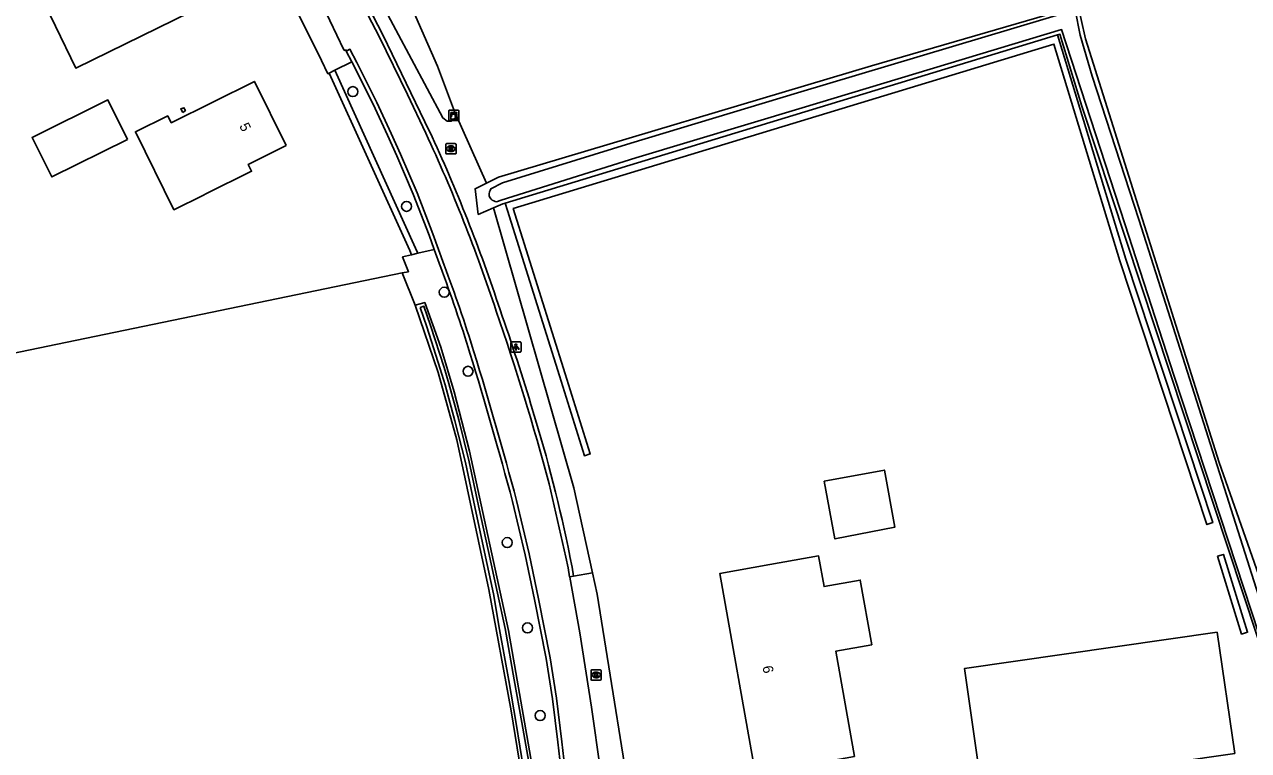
# Model space of a CAD drawing. Extents: x 162515 to 163909, y 388494 to 389773.
# Drawn here: x 163081.8 to 163201.7, y 389600.1 to 389671.2 of the extents above; entities that cross this region are included whole.
import ezdxf

# ---------------------------------------------------------------- set-up
doc = ezdxf.new("R2010")
doc.units = 0
for name, color, linetype in [('IMGEO_Boom', 7, 'Continuous'), ('IMGEO_Erf', 7, 'Continuous'), ('IMGEO_Grasland_agrarisch', 7, 'Continuous'), ('IMGEO_Grasland_overig', 7, 'Continuous'), ('IMGEO_Haag', 7, 'Continuous'), ('IMGEO_Kast', 7, 'Continuous'), ('IMGEO_Kolk', 7, 'Continuous'), ('IMGEO_Lichtpunt', 7, 'Continuous'), ('IMGEO_Pand', 7, 'Continuous'), ('IMGEO_Pand_nummerreeks', 7, 'Continuous'), ('IMGEO_Rijbaan_lokaal_gesloten', 7, 'Continuous'), ('IMGEO_Rijbaan_lokaal_halfverhard', 7, 'Continuous'), ('IMGEO_Rijbaan_lokaal_open', 7, 'Continuous'), ('IMGEO_Rioolput', 7, 'Continuous'), ('IMGEO_Sloot', 7, 'Continuous'), ('IMGEO_Waterloop', 7, 'Continuous')]:
    doc.layers.add(name, color=color, linetype=linetype)

msp = doc.modelspace()

# ---------------------------------------------------------------- linework, layer by layer
at = {"layer": 'IMGEO_Boom'}
for centre in [(163113.98, 389664.61), (163119.24, 389653.38), (163122.93, 389644.98), (163125.26, 389637.24), (163129.1, 389620.48), (163131.08, 389612.13), (163132.32, 389603.55)]:
    msp.add_circle(centre, 0.489, dxfattribs=at)
at = {"layer": 'IMGEO_Erf'}
for points in [[(163182.98, 389670.17), (163183.2, 389670.23), (163185.36, 389663.19), (163202.54, 389611.21), (163206.56, 389587.55), (163208.34, 389574.96), (163210.99, 389575.22)], [(163127.75, 389653.25), (163128.66, 389653.64), (163128.88, 389653.71)]]:
    msp.add_lwpolyline(points, dxfattribs=at)
at = {"layer": 'IMGEO_Grasland_agrarisch'}
for points in [[(163118.81, 389646.87), (163066.29, 389636.03), (163063.36, 389648.6), (163049.05, 389695.77), (163050.19, 389696.14), (163051.31, 389696.5), (163053.35, 389697.16), (163060.78, 389699.57), (163079.14, 389705.13), (163083.99, 389706.6)], [(163127.06, 389655.65), (163128.25, 389656.23), (163164.76, 389667.14), (163184.98, 389673), (163185.27, 389671.67)], [(163204.95, 389610.01), (163204.59, 389611.79), (163198.78, 389628.32), (163185.7, 389669.77), (163185.27, 389671.67)], [(163130.74, 389593.91), (163130.82, 389595.75), (163129.49, 389604.01), (163127.31, 389615.89), (163124.17, 389630.54), (163122.35, 389637.11), (163120.08, 389643.72)]]:
    msp.add_lwpolyline(points, dxfattribs=at)
at = {"layer": 'IMGEO_Grasland_overig'}
for points in [[(163127.06, 389655.65), (163123.95, 389662.66)], [(163127.75, 389653.25), (163126.26, 389652.6), (163125.95, 389655.11), (163127.06, 389655.65)], [(163137.44, 389617.53), (163135.63, 389625.83), (163127.75, 389653.25)], [(163120.34, 389648.79), (163121.96, 389649.17)], [(163119.74, 389648.65), (163118.86, 389648.44), (163119.43, 389646.99), (163118.81, 389646.87)], [(163120.08, 389643.72), (163118.81, 389646.87)], [(163120.08, 389643.72), (163120.56, 389643.84), (163121.03, 389643.96), (163122.6, 389639.6), (163123.9, 389635.22), (163125.4, 389629.44), (163129.21, 389611.86), (163131.99, 389595.99), (163132.04, 389595.09), (163132.1, 389594.03)]]:
    msp.add_lwpolyline(points, dxfattribs=at)
at = {"layer": 'IMGEO_Haag'}
for points in [[(163128.88, 389653.71), (163129.11, 389652.98), (163134.21, 389636.8), (163136.65, 389628.98), (163137.23, 389629.16), (163134.78, 389636.98), (163129.68, 389653.16), (163182.62, 389669.26), (163189.08, 389648.04), (163197.59, 389622.24), (163198.16, 389622.43), (163189.65, 389648.22), (163182.98, 389670.17)], [(163182.98, 389670.17), (163128.88, 389653.71)], [(163111.68, 389666.43), (163119.56, 389649.05), (163119.74, 389648.65)], [(163112.22, 389666.7), (163120.11, 389649.3), (163120.34, 389648.79)], [(163119.74, 389648.65), (163120.34, 389648.79)], [(163198.64, 389619.15), (163200.99, 389611.52), (163201.57, 389611.7), (163199.21, 389619.32), (163198.64, 389619.15)]]:
    msp.add_lwpolyline(points, dxfattribs=at)
at = {"layer": 'IMGEO_Kast'}
for p, q in [((163123.37, 389661.86), (163123.37, 389662.71)), ((163123.37, 389662.71), (163123.37, 389661.86)), ((163123.44, 389662.79), (163124.28, 389662.79)), ((163124.28, 389662.79), (163123.44, 389662.79)), ((163124.37, 389662.72), (163124.37, 389661.87)), ((163124.37, 389661.87), (163124.37, 389662.72)), ((163124.29, 389661.79), (163123.45, 389661.79)), ((163123.45, 389661.79), (163124.29, 389661.79))]:
    msp.add_line(p, q, dxfattribs=at)
for points in [[(163123.56, 389662.58), (163124.16, 389662.58), (163124.16, 389662.49), (163123.56, 389662.49), (163123.56, 389662.58)], [(163123.56, 389662.41), (163124.16, 389662.41), (163124.16, 389661.92), (163123.56, 389661.92), (163123.56, 389662.41)]]:
    msp.add_lwpolyline(points, dxfattribs=at)
msp.add_circle((163123.65, 389662.25), 0.0377, dxfattribs=at)
for centre, start, end in [((163123.45, 389662.71), 92.4484, 184.2845), ((163123.45, 389662.71), 92.4484, 184.2845), ((163124.29, 389662.71), 2.4484, 94.2845), ((163124.29, 389662.71), 2.4484, 94.2845), ((163123.45, 389661.87), 182.4484, 274.2845), ((163123.45, 389661.87), 182.4484, 274.2845), ((163124.29, 389661.87), 272.4484, 4.2845), ((163124.29, 389661.87), 272.4484, 4.2845)]:
    msp.add_arc(centre, 0.0779, start, end, dxfattribs=at)
at = {"layer": 'IMGEO_Kolk'}
for p, q in [((163137.37, 389608.03), (163138.22, 389608.03)), ((163137.3, 389607.1), (163137.3, 389607.96)), ((163138.22, 389607.03), (163137.37, 389607.03)), ((163137.78, 389607.81), (163137.81, 389607.81)), ((163137.81, 389607.25), (163137.78, 389607.25)), ((163138.3, 389607.96), (163138.3, 389607.1))]:
    msp.add_line(p, q, dxfattribs=at)
for points in [[(163137.37, 389608.03), (163138.22, 389608.03)], [(163137.3, 389607.1), (163137.3, 389607.96)], [(163138.22, 389607.03), (163137.37, 389607.03)], [(163137.62, 389607.73), (163137.74, 389607.73), (163137.74, 389607.58), (163137.87, 389607.73), (163138.03, 389607.73), (163137.89, 389607.58), (163138.04, 389607.33), (163137.89, 389607.33), (163137.8, 389607.49), (163137.74, 389607.43), (163137.74, 389607.33), (163137.62, 389607.33), (163137.62, 389607.73)], [(163138.3, 389607.96), (163138.3, 389607.1)]]:
    msp.add_lwpolyline(points, dxfattribs=at)
for centre, start, end in [((163137.37, 389607.95), 91.552, 178.448), ((163137.37, 389607.95), 91.552, 178.448), ((163138.22, 389607.95), 1.552, 88.448), ((163138.22, 389607.95), 1.552, 88.448), ((163137.37, 389607.1), 181.552, 268.448), ((163137.37, 389607.1), 181.552, 268.448), ((163138.22, 389607.1), 271.552, 358.448), ((163138.22, 389607.1), 271.552, 358.448)]:
    msp.add_arc(centre, 0.0765, start, end, dxfattribs=at)
for centre, major_axis, ratio, start_param, end_param in [((163137.78, 389607.53), (-0.387, 0.002), 0.722429, 4.712389, 7.853982), ((163137.81, 389607.53), (-0.39, 0.002), 0.717154, 1.570796, 4.712389)]:
    msp.add_ellipse(centre, major_axis=major_axis, ratio=ratio, start_param=start_param, end_param=end_param, dxfattribs=at)
at = {"layer": 'IMGEO_Lichtpunt'}
for p, q in [((163129.45, 389640.02), (163129.45, 389639.21)), ((163129.45, 389640.02), (163129.45, 389639.21)), ((163130.35, 389640.11), (163129.55, 389640.11)), ((163130.35, 389640.11), (163129.55, 389640.11)), ((163130.45, 389639.21), (163130.45, 389640.02)), ((163130.45, 389639.21), (163130.45, 389640.02)), ((163129.55, 389639.11), (163130.35, 389639.11)), ((163129.55, 389639.11), (163130.35, 389639.11))]:
    msp.add_line(p, q, dxfattribs=at)
for points in [[(163129.83, 389639.68), (163129.87, 389639.65), (163129.68, 389639.39), (163129.64, 389639.42), (163129.83, 389639.68)], [(163129.93, 389639.63), (163129.98, 389639.63), (163129.98, 389639.31), (163129.93, 389639.31), (163129.93, 389639.63)], [(163130.04, 389639.65), (163130.08, 389639.68), (163130.26, 389639.42), (163130.23, 389639.39), (163130.04, 389639.65)]]:
    msp.add_lwpolyline(points, dxfattribs=at)
msp.add_circle((163129.95, 389639.81), 0.0994, dxfattribs=at)
for centre, start, end in [((163129.55, 389640.02), 90, 180), ((163129.55, 389640.02), 90, 180), ((163129.55, 389639.21), 180, 270), ((163129.55, 389639.21), 180, 270), ((163130.35, 389640.02), 0, 90), ((163130.35, 389640.02), 0, 90), ((163130.35, 389639.21), 270, 0), ((163130.35, 389639.21), 270, 360)]:
    msp.add_arc(centre, 0.0946, start, end, dxfattribs=at)
at = {"layer": 'IMGEO_Pand'}
for points in [[(163098.55, 389677.48), (163096.01, 389682.67), (163091.52, 389680.48), (163089.07, 389679.29), (163089.78, 389677.83), (163083.13, 389674.59), (163084.86, 389671.03), (163086.86, 389666.92), (163099.73, 389673.2), (163097.81, 389677.12), (163098.55, 389677.48)], [(163107.46, 389659.34), (163103.75, 389657.49), (163104.07, 389656.82), (163099.59, 389654.6), (163099.36, 389654.49), (163096.47, 389653.05), (163092.7, 389660.69), (163095.86, 389662.23), (163096.2, 389661.57), (163104.35, 389665.61), (163107.46, 389659.34)], [(163091.92, 389659.94), (163084.5, 389656.26), (163082.59, 389660.11), (163090.01, 389663.8), (163091.92, 389659.94)], [(163097.33, 389662.56), (163097.13, 389662.91), (163097.45, 389663.03), (163097.6, 389662.75), (163097.33, 389662.56)], [(163160.12, 389626.49), (163166.02, 389627.57), (163167.03, 389621.98), (163161.17, 389620.83), (163160.12, 389626.49)], [(163154.82, 389618.32), (163159.58, 389619.17), (163160.12, 389616.18), (163163.66, 389616.81), (163164.79, 389610.48), (163161.25, 389609.85), (163163.08, 389599.55), (163158.32, 389598.71), (163153.4, 389597.83), (163149.9, 389617.44), (163154.82, 389618.32)], [(163198.61, 389611.71), (163200.32, 389599.85), (163175.56, 389596.29), (163173.86, 389608.15), (163198.61, 389611.71)]]:
    msp.add_lwpolyline(points, dxfattribs=at)
at = {"layer": 'IMGEO_Rijbaan_lokaal_gesloten'}
for points in [[(163121.13, 389660.55), (163119.32, 389664.34), (163116.56, 389670), (163115.13, 389672.76), (163113.12, 389676.63), (163110.97, 389680.47), (163108.78, 389684.31), (163105.61, 389689.69), (163102.22, 389695.47)], [(163111.06, 389673.02), (163113.09, 389668.69), (163113.23, 389668.65), (163113.32, 389668.69), (163113.38, 389668.6)], [(163113.38, 389668.6), (163113.69, 389668.75), (163114.37, 389667.45), (163116.33, 389663.55), (163117.75, 389660.51), (163118.65, 389658.48), (163120.27, 389654.71), (163121.83, 389650.7), (163122.93, 389647.62)], [(163135.2, 389617.13), (163135.05, 389618.01), (163134.84, 389619.05), (163133.21, 389626.24)], [(163130.01, 389624.59), (163131.24, 389619.38), (163132.17, 389614.98), (163133.3, 389609.2), (163133.91, 389605.25), (163134.45, 389600.99), (163135.22, 389594.21), (163135.78, 389589.73), (163135.99, 389588.08)], [(163139.43, 389588.1), (163138.22, 389598.19), (163137.34, 389604.37), (163136.22, 389611.66), (163135.21, 389617.1), (163135.2, 389617.13)]]:
    msp.add_lwpolyline(points, dxfattribs=at)
for centre, radius, start, end in [((162975.94, 389593.05), 160.11, 18.224, 24.9337), ((162971.6, 389591.12), 161.54, 17.2931, 20.4708), ((162904.39, 389565.14), 236.83, 14.9509, 19.225), ((162761.45, 389526.73), 381.33, 14.8706, 17.145)]:
    msp.add_arc(centre, radius, start, end, dxfattribs=at)
at = {"layer": 'IMGEO_Rijbaan_lokaal_halfverhard'}
for points in [[(163121.49, 389660.72), (163116.92, 389670.18), (163115.49, 389672.95), (163113.47, 389676.83), (163111.32, 389680.67), (163109.12, 389684.51), (163105.96, 389689.9)], [(163113.87, 389667.51), (163115.97, 389663.38), (163117.39, 389660.34), (163118.29, 389658.32), (163119.9, 389654.56), (163121.46, 389650.56), (163121.96, 389649.17)], [(163121.96, 389649.17), (163122.56, 389647.48)], [(163129.62, 389624.5), (163130.85, 389619.29), (163131.78, 389614.91), (163132.9, 389609.13), (163133.52, 389605.2), (163134.05, 389600.94), (163134.82, 389594.16), (163135.39, 389589.68), (163135.59, 389588.03), (163135.99, 389588.08)], [(163135.6, 389617.2), (163135.44, 389618.08), (163135.23, 389619.13)]]:
    msp.add_lwpolyline(points, dxfattribs=at)
for centre, radius, start, end in [((162975.89, 389593.03), 160.57, 18.2291, 24.9353), ((162972.42, 389591.4), 160.27, 17.2878, 20.4824), ((162908.57, 389566.51), 232.84, 16.684, 19.246), ((162759.15, 389526.06), 383.32, 14.8802, 17.1387), ((162999.11, 389592), 138.8, 11.2737, 17.3347)]:
    msp.add_arc(centre, radius, start, end, dxfattribs=at)
at = {"layer": 'IMGEO_Rijbaan_lokaal_open'}
for points in [[(163108.67, 389672.19), (163110.9, 389667.66), (163111.54, 389666.36), (163111.68, 389666.43)], [(163113.38, 389668.6), (163113.33, 389668.58), (163113.87, 389667.51)], [(163112.22, 389666.7), (163113.87, 389667.51)], [(163111.68, 389666.43), (163112.22, 389666.7)], [(163135.2, 389617.13), (163135.6, 389617.2)], [(163135.6, 389617.2), (163137.44, 389617.53)], [(163137.44, 389617.53), (163137.9, 389615.42), (163141.86, 389590.82), (163142.03, 389590.07)]]:
    msp.add_lwpolyline(points, dxfattribs=at)
at = {"layer": 'IMGEO_Rioolput'}
for p, q in [((163123.16, 389659.52), (163124.01, 389659.52)), ((163123.08, 389658.59), (163123.08, 389659.44)), ((163124.01, 389658.52), (163123.16, 389658.52)), ((163123.57, 389659.3), (163123.6, 389659.3)), ((163123.59, 389658.74), (163123.57, 389658.74)), ((163124.09, 389659.44), (163124.09, 389658.59))]:
    msp.add_line(p, q, dxfattribs=at)
for points in [[(163123.16, 389659.52), (163124.01, 389659.52)], [(163123.08, 389658.59), (163123.08, 389659.44)], [(163124.01, 389658.52), (163123.16, 389658.52)], [(163123.67, 389659.21), (163123.42, 389659.22), (163123.42, 389658.82)], [(163123.42, 389658.82), (163123.55, 389658.82), (163123.55, 389658.98), (163123.56, 389658.98)], [(163123.6, 389659.14), (163123.55, 389659.14), (163123.55, 389659.05)], [(163123.55, 389659.05), (163123.6, 389659.05)], [(163123.6, 389658.95), (163123.67, 389658.82), (163123.81, 389658.82), (163123.75, 389658.94)], [(163124.09, 389659.44), (163124.09, 389658.59)]]:
    msp.add_lwpolyline(points, dxfattribs=at)
for centre, radius, start, end in [((163123.16, 389659.44), 0.0765, 91.552, 178.448), ((163123.16, 389659.44), 0.0765, 91.552, 178.448), ((163124.01, 389659.44), 0.0765, 1.552, 88.448), ((163124.01, 389659.44), 0.0765, 1.552, 88.448), ((163123.16, 389658.59), 0.0765, 181.552, 268.448), ((163123.16, 389658.59), 0.0765, 181.552, 268.448), ((163123.55, 389658.93), 0.0533, 26.0293, 88.6989), ((163123.6, 389659.04), 0.0964, 77.0061, 93.1865), ((163123.58, 389659.24), 0.19, 274.7715, 282.9687), ((163123.62, 389659.1), 0.0378, 276.6634, 79.6772), ((163123.67, 389659.11), 0.109, 350.3612, 89.416), ((163123.67, 389659.1), 0.112, 277.5842, 350.9817), ((163123.65, 389658.89), 0.108, 29.5134, 73.7905), ((163124.01, 389658.59), 0.0765, 271.552, 358.448), ((163124.01, 389658.59), 0.0765, 271.552, 358.448)]:
    msp.add_arc(centre, radius, start, end, dxfattribs=at)
for centre, major_axis, ratio, start_param, end_param in [((163123.57, 389659.02), (-0.387, 0.002), 0.722429, 4.712389, 7.853982), ((163123.6, 389659.02), (-0.39, 0.002), 0.717154, 1.570796, 4.712389)]:
    msp.add_ellipse(centre, major_axis=major_axis, ratio=ratio, start_param=start_param, end_param=end_param, dxfattribs=at)
at = {"layer": 'IMGEO_Sloot'}
for points in [[(163123.95, 389662.66), (163122.28, 389667.1), (163118.6, 389675.44), (163119.39, 389675.84), (163128.29, 389678.66), (163138.31, 389681.76), (163145.34, 389683.97), (163153.6, 389686.6), (163174.85, 389693.27), (163221.12, 389707.01), (163255, 389715.89), (163280.24, 389722.61), (163285.76, 389724.09), (163286.57, 389722.49), (163287.5, 389718.95), (163287.69, 389719), (163287.81, 389719.03), (163288.07, 389719.1)], [(163108.1, 389691.14), (163107.87, 389691.02), (163107.76, 389690.16), (163108.13, 389689.14), (163113.58, 389679.31), (163122.8, 389662.04), (163123.23, 389661.71), (163123.61, 389661.72), (163124.04, 389662.03), (163123.95, 389662.66)]]:
    msp.add_lwpolyline(points, dxfattribs=at)
at = {"layer": 'IMGEO_Waterloop'}
for points in [[(163127.36, 389654.81), (163127.42, 389654.95), (163127.49, 389655.1), (163128.65, 389655.68), (163141.2, 389659.58), (163157.51, 389664.5), (163184.71, 389672.63), (163185.18, 389670.12), (163186.36, 389666.11), (163190.93, 389652.11), (163195.7, 389637.16), (163203.77, 389611.71), (163205.31, 389601.98), (163207.46, 389588.09), (163208.42, 389584.17), (163209.29, 389580.64), (163210.38, 389576.22), (163210.35, 389576.08), (163210.31, 389575.95)], [(163189.57, 389651.67), (163183.37, 389670.68), (163157.96, 389663.03), (163141.7, 389658.12), (163128.51, 389654), (163128.06, 389653.81)], [(163209.32, 389575.82), (163206.7, 389587.88), (163204.55, 389601.86), (163202.71, 389611.45), (163194.4, 389636.75), (163189.57, 389651.67)], [(163120.57, 389643.49), (163120.94, 389643.62), (163121.6, 389641.71), (163122.91, 389637.6), (163123.39, 389636.04), (163124.35, 389632.5), (163125.38, 389628.39), (163126.3, 389624.07), (163127.25, 389619.62), (163128.14, 389615.53), (163128.88, 389612.07), (163129.78, 389607.05), (163130.53, 389602.87), (163131.31, 389598.43)], [(163130.7, 389598.35), (163129.96, 389602.78), (163129.26, 389606.97), (163128.33, 389611.97), (163127.76, 389615.45), (163126.87, 389619.54), (163125.92, 389623.99), (163125, 389628.3), (163123.97, 389632.4), (163123.01, 389635.93), (163122.54, 389637.48), (163121.23, 389641.59), (163120.57, 389643.49)]]:
    msp.add_lwpolyline(points, dxfattribs=at)
for centre, radius, start, end in [((163128.01, 389654.57), 0.691, 159.7772, 224.542), ((163128.27, 389654.92), 1.13, 227.9029, 259.5508)]:
    msp.add_arc(centre, radius, start, end, dxfattribs=at)

# ---------------------------------------------------------------- texts
at = {"layer": 'IMGEO_Pand_nummerreeks'}
for s, rotation, p in [('5', 296.3489, (163102.84, 389661.26)), ('6', 280.1166, (163154.08, 389608.35))]:
    msp.add_text(s, height=1, rotation=rotation, dxfattribs=at).set_placement(p)

doc.saveas('drawing.dxf')
